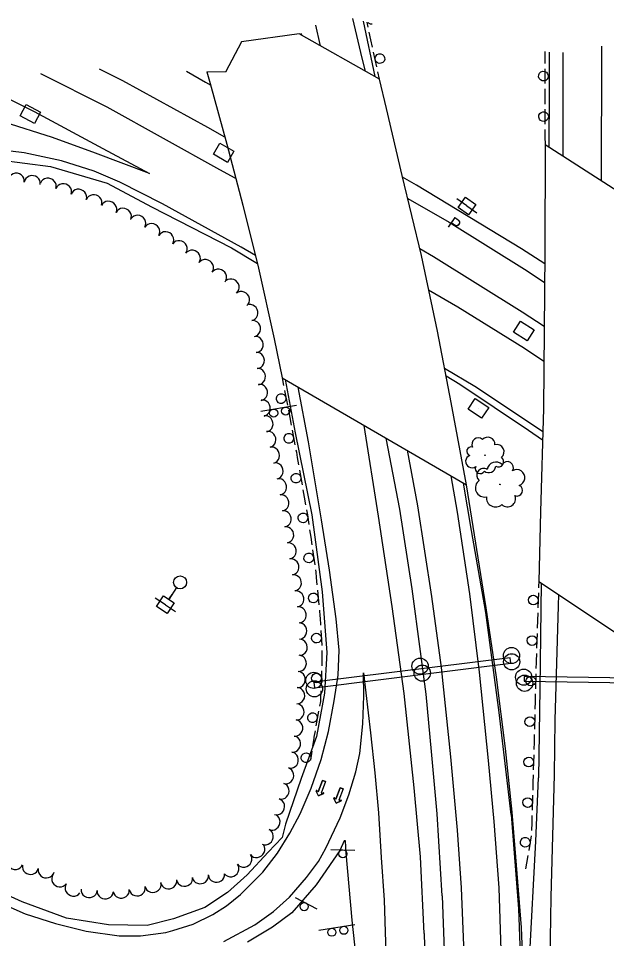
# Model space of a CAD drawing. Extents: x 1746010 to 1754829, y 655801 to 663091.
# Drawn here: x 1753661 to 1754024, y 656968 to 657536 of the extents above; entities that cross this region are included whole.
import ezdxf

# ---------------------------------------------------------------- set-up
doc = ezdxf.new("R2010")
doc.units = 0
for name, color, linetype in [('SURVEY - AERIAL SURVEY - Photo Control - Points - Elevations', 7, 'Continuous'), ('SURVEY - AERIAL SURVEY - Photo Control - Points - Locators', 7, 'Continuous'), ('SURVEY - AERIAL SURVEY - Photo Control - Points - Numbers', 7, 'Continuous'), ('SURVEY - AERIAL SURVEY - Photo Control with Text', 7, 'Continuous'), ('SURVEY - CENTERLINE - Existing Roads Curve Text', 7, 'Continuous'), ('SURVEY - CENTERLINE - Existing Roads Text', 7, 'Continuous'), ('SURVEY - CENTERLINE - Preliminary - Development', 7, 'Continuous'), ('SURVEY - DRAINAGE - Area Shapes - Points - Elevations', 7, 'Continuous')]:
    doc.layers.add(name, color=color, linetype=linetype)

msp = doc.modelspace()

# ---------------------------------------------------------------- linework, layer by layer
at = {"layer": 'SURVEY - AERIAL SURVEY - Photo Control - Points - Elevations'}
for p, q in [((1753834.37, 657526.97), (1753798.75, 657521.92)), ((1753883.94, 657498.81), (1753834.37, 657526.97)), ((1753798.75, 657521.92), (1753789.02, 657503.21)), ((1753789.02, 657503.21), (1753777.4, 657503.5)), ((1753777.4, 657503.5), (1753779.59, 657496.21)), ((1753888.34, 657480.7), (1753883.94, 657498.81)), ((1753779.59, 657496.21), (1753789.79, 657458.68)), ((1753897.95, 657439.39), (1753888.34, 657480.7)), ((1753789.79, 657458.68), (1753799.56, 657421.07)), ((1753909.88, 657390.08), (1753897.95, 657439.39)), ((1753799.56, 657421.07), (1753809.34, 657382.31)), ((1753919.69, 657343.31), (1753909.88, 657390.08)), ((1753809.34, 657382.31), (1753818.96, 657338.7)), ((1753818.96, 657338.7), (1753823.91, 657314.53)), ((1753928.26, 657299.26), (1753919.69, 657343.31)), ((1753823.91, 657314.53), (1753937.73, 657248.53)), ((1753937.73, 657248.53), (1753928.26, 657299.26))]:
    msp.add_line(p, q, dxfattribs=at)
for points in [[(1753982.28, 657188.73), (1754080.08, 657123.8), (1754080.93, 657167.72), (1754082.29, 657253.87), (1754084.25, 657323.66), (1754089.74, 657391.89), (1753986.12, 657458.37), (1753985.99, 657391.93), (1753985.12, 657295.57), (1753983.31, 657231.76)], [(1753983.31, 657231.76), (1753982.28, 657188.73)]]:
    msp.add_lwpolyline(points, dxfattribs=at)
at = {"layer": 'SURVEY - AERIAL SURVEY - Photo Control - Points - Locators'}
for points in [[(1753844.48, 657532.15), (1753847.2, 657520.24), (1753847.35, 657519.6)], [(1753875.26, 657503.74), (1753873.37, 657511.78), (1753867.51, 657536.41)], [(1753874, 657534.62), (1753881.04, 657500.46)], [(1753835.53, 657527.36), (1753835.78, 657526.17)], [(1753988.75, 657515.59), (1753988.61, 657491.19), (1753988.56, 657456.81)], [(1753997.21, 657515.41), (1753997.06, 657451.35)], [(1754020.92, 657436.04), (1754020.94, 657441.6), (1754021.2, 657510.2), (1754021.13, 657519.32)], [(1753788.6, 657463.06), (1753778.14, 657469.07), (1753725.62, 657497.78), (1753711.2, 657505.1)], [(1753764.93, 657503.8), (1753776.54, 657497.13), (1753779.86, 657495.22)], [(1753674.79, 657502.49), (1753715.63, 657481.77), (1753785.31, 657443.07), (1753794.78, 657437.97), (1753795.24, 657437.7)], [(1753637.56, 657495.57), (1753670.88, 657478.92), (1753713.29, 657456.11), (1753741.97, 657440.63), (1753708.7, 657453.2), (1753682.13, 657462.88), (1753652.37, 657472.36)], [(1753807.41, 657389.96), (1753798.71, 657395.14), (1753750.15, 657422.01), (1753723.66, 657435.28), (1753707.83, 657442.08), (1753687.72, 657448.46), (1753664.76, 657453.46), (1753637.56, 657456.66)], [(1753648.98, 657449.1), (1753680.95, 657444.97), (1753716, 657434.66), (1753743.3, 657420.04), (1753792.57, 657394.69), (1753808.62, 657385.12)], [(1753985.93, 657384.86), (1753971.69, 657394.13), (1753906.82, 657433.55), (1753898.17, 657438.46)], [(1753901.37, 657425.25), (1753926.89, 657410.56), (1753975.06, 657380.49), (1753985.82, 657373.37)], [(1753985.58, 657346.15), (1753972.07, 657355.07), (1753917.41, 657389.22), (1753908.91, 657394.1)], [(1753914.32, 657368.9), (1753932.37, 657358.47), (1753973.51, 657332.85), (1753985.39, 657324.89)], [(1753984.71, 657281.22), (1753975.27, 657287.62), (1753942.8, 657309.25), (1753924.15, 657320.36)], [(1753925.05, 657315.77), (1753933.59, 657310.68), (1753975.97, 657282.33), (1753984.57, 657276.37)], [(1753825.7, 657313.49), (1753831.86, 657280.52), (1753842.22, 657229.94), (1753848.55, 657182.4), (1753851.43, 657145.05), (1753849.98, 657119.99), (1753845.04, 657093.08), (1753835.56, 657067.29), (1753825.92, 657038.96), (1753823.95, 657030.83), (1753815.35, 657021.8), (1753802.32, 657007.78), (1753790.24, 656996.9), (1753776.23, 656987.66), (1753756.79, 656980.5), (1753740.58, 656976.5), (1753716.66, 656976.82), (1753690.8, 656981.07), (1753663.52, 656991.15), (1753640.25, 657001.61)], [(1753645.14, 656992.62), (1753665.32, 656983.72), (1753683.97, 656977.73), (1753703.07, 656972.98), (1753723.39, 656970.11), (1753736.43, 656970.12), (1753752.08, 656972.06), (1753756.55, 656973.32), (1753768.99, 656977.37), (1753781.07, 656983.19), (1753789.65, 656988.64), (1753798.13, 656995.69), (1753811.95, 657009.37), (1753821.07, 657021.17), (1753828.6, 657033.44), (1753834.93, 657045.36), (1753841.82, 657061.31), (1753848.04, 657078.86), (1753852.57, 657096.17), (1753856.07, 657115.13), (1753858.57, 657131.1), (1753859.12, 657146.45), (1753857.25, 657165.69), (1753853.03, 657195.87), (1753848.19, 657226.85), (1753840.16, 657275.06), (1753833.88, 657308.74)], [(1753911.58, 656971.59), (1753909.19, 657018.77), (1753905.31, 657061.37), (1753899.14, 657119.66), (1753891.84, 657173.33), (1753883.28, 657229.17), (1753874.58, 657285.15)], [(1753901.01, 657269.83), (1753907.47, 657235.62), (1753916.07, 657179.56), (1753922.04, 657135.77), (1753927.79, 657080.63), (1753932, 657035.33), (1753934.34, 656999.68)], [(1753954.79, 657040.59), (1753951.33, 657078.32), (1753945.71, 657132.8), (1753939.71, 657181.2), (1753932.16, 657231.59), (1753928.27, 657254.02)], [(1753965.29, 657045.03), (1753957.84, 657108.02), (1753949.52, 657169.69), (1753940.73, 657220.37), (1753935.87, 657249.61)], [(1753983.71, 657187.78), (1753983, 657122.71), (1753982.03, 657067.54)], [(1753994.37, 657180.7), (1753994.21, 657173.78), (1753992.14, 657103.3), (1753991.68, 657069.51)], [(1753787.96, 656966.58), (1753807.07, 656976.95), (1753818.65, 656985.21), (1753828.41, 656993.91), (1753838.96, 657006.11), (1753846.27, 657016.03), (1753850.85, 657024.12), (1753859.8, 657042.93), (1753865.11, 657057.06), (1753869.43, 657071.44), (1753871.86, 657082.68), (1753873.77, 657100.96), (1753874.4, 657118.17), (1753874.11, 657132.54), (1753878.36, 657095.43), (1753881.01, 657070.7), (1753883.3, 657046.01), (1753885.02, 657018.43), (1753886.83, 656992.14), (1753888.03, 656953.03)], [(1753965.29, 657045.03), (1753969.78, 656986.81), (1753972.15, 656919.55), (1753972.04, 656909.9), (1753975.16, 656909.61), (1753976.56, 656955.34), (1753980.46, 657028.6), (1753982.03, 657067.54)], [(1753991.68, 657069.51), (1753989.79, 656994.07), (1753988.51, 656917.34), (1753987.63, 656845.93), (1753986.9, 656777.13), (1753986.19, 656713.33), (1753984.5, 656618.92), (1753983.53, 656530.59), (1753982.02, 656453.23), (1753981.29, 656391.76), (1753979.87, 656290.99), (1753978.52, 656188.25), (1753977.29, 656086), (1753975.64, 655980.75), (1753974.7, 655894.53), (1753973.26, 655807.54)], [(1753945.21, 655807.54), (1753945.71, 655839.43), (1753947.46, 655954.84), (1753949.86, 656090.09), (1753951.64, 656208.18), (1753953.96, 656365.1), (1753956.15, 656510.33), (1753958.33, 656633.76), (1753960.21, 656768.19), (1753961.13, 656897.07), (1753957.75, 656999.64), (1753954.79, 657040.59)], [(1753873.7, 656918.81), (1753867.13, 656979.71), (1753863.36, 657021.42), (1753862.98, 657028.83), (1753862.1, 657028.66), (1753859.42, 657022.88), (1753844.95, 657001.52), (1753829.84, 656984.34), (1753818.01, 656975.55), (1753802.43, 656966.23)], [(1753934.34, 656999.68), (1753937.35, 656928.49), (1753937.83, 656848.86), (1753937.15, 656768.64), (1753935.67, 656669.84), (1753934.34, 656582.14), (1753932.9, 656495.46), (1753931.11, 656385.87), (1753929.83, 656290.6), (1753928.48, 656204.07), (1753926.32, 656083.91), (1753924.94, 655990.25), (1753923.13, 655865.62), (1753922.15, 655807.78)], [(1753911.58, 656971.59), (1753912.64, 656934.08), (1753912.82, 656887.25), (1753912.7, 656839.09), (1753911.76, 656786.44), (1753911.02, 656744.09), (1753910.41, 656695.47), (1753910.01, 656636.87), (1753909.36, 656581.72), (1753908.73, 656535.43), (1753907.55, 656485.64), (1753906.86, 656418.94), (1753906.17, 656369.03), (1753905.58, 656318.08), (1753904.54, 656261.45), (1753903.46, 656192.68), (1753902.26, 656132.87), (1753901.8, 656071.81), (1753900.44, 656014.99), (1753899.79, 655943.06), (1753898.72, 655891.08), (1753897.3, 655813.85), (1753897.22, 655808.04)]]:
    msp.add_lwpolyline(points, dxfattribs=at)
at = {"layer": 'SURVEY - AERIAL SURVEY - Photo Control - Points - Numbers'}
for points in [[(1753876.95, 657530.95), (1753876.29, 657533.99)], [(1753834.54, 657526.87), (1753834.52, 657526.99)], [(1753878.63, 657523.23), (1753877.63, 657527.82)], [(1753879.63, 657518.64), (1753878.63, 657523.23)], [(1753882.26, 657506.53), (1753880.31, 657515.51)], [(1753985.92, 657516), (1753985.93, 657513.23)], [(1753985.93, 657513.23), (1753985.95, 657508.54)], [(1753883.94, 657498.81), (1753882.94, 657503.4)], [(1753985.96, 657505.33), (1753985.99, 657496.13)], [(1753986, 657492.93), (1753986.02, 657488.23)], [(1753986.02, 657488.23), (1753986.03, 657483.53)], [(1753986.04, 657480.33), (1753986.07, 657471.13)], [(1753986.09, 657467.93), (1753986.1, 657463.23)], [(1753986.1, 657463.23), (1753986.12, 657458.53)], [(1753823.91, 657314.53), (1753824.79, 657309.91)], [(1753825.4, 657306.77), (1753827.13, 657297.73)], [(1753827.73, 657294.59), (1753828.61, 657289.98)], [(1753828.61, 657289.98), (1753829.5, 657285.36)], [(1753830.1, 657282.22), (1753831.83, 657273.19)], [(1753922.72, 656994.79), (1753919.67, 657045.5), (1753916.14, 657083.96), (1753912.8, 657119.26), (1753909.25, 657145.57), (1753904.05, 657184.38), (1753896.51, 657233.47), (1753888.15, 657277.28)], [(1753832.43, 657270.05), (1753832.68, 657268.75), (1753833.27, 657265.42)], [(1753833.27, 657265.42), (1753834.08, 657260.79)], [(1753834.63, 657257.64), (1753836.22, 657248.58)], [(1753965.85, 657046.35), (1753961.67, 657085.64), (1753956.14, 657129.7), (1753949.81, 657172.53), (1753937.73, 657248.53)], [(1753836.77, 657245.42), (1753837.58, 657240.8)], [(1753837.58, 657240.8), (1753838.39, 657236.17)], [(1753838.95, 657233.01), (1753839.47, 657230.04), (1753840.36, 657223.93)], [(1753840.83, 657220.76), (1753841.51, 657216.12)], [(1753841.51, 657216.12), (1753842.19, 657211.47)], [(1753842.65, 657208.3), (1753843.99, 657199.21)], [(1753844.45, 657196.04), (1753844.65, 657194.66), (1753844.97, 657191.37)], [(1753844.97, 657191.37), (1753845.41, 657186.69)], [(1753982.3, 657189.69), (1753982.14, 657184.99)], [(1753845.71, 657183.51), (1753846.59, 657174.35)], [(1753982.03, 657181.8), (1753981.73, 657172.6)], [(1753846.89, 657171.16), (1753847.24, 657167.47), (1753847.31, 657166.48)], [(1753981.62, 657169.41), (1753981.46, 657164.71)], [(1753847.31, 657166.48), (1753847.61, 657161.79)], [(1753981.46, 657164.71), (1753981.3, 657160.01)], [(1753847.81, 657158.6), (1753848.38, 657149.6), (1753848.38, 657149.42)], [(1753981.19, 657156.81), (1753980.89, 657147.62)], [(1753848.36, 657146.22), (1753848.33, 657141.52)], [(1753848.33, 657141.52), (1753848.31, 657136.82)], [(1753980.62, 657139.73), (1753980.59, 657138.73), (1753980.49, 657135.03)], [(1753980.78, 657144.42), (1753980.62, 657139.73)], [(1753848.29, 657133.62), (1753848.28, 657133.31), (1753847.9, 657124.44)], [(1753980.41, 657131.83), (1753980.18, 657122.63)], [(1753847.77, 657121.24), (1753847.56, 657116.55)], [(1753980.1, 657119.43), (1753979.98, 657114.73)], [(1753847.56, 657116.55), (1753847.49, 657114.81), (1753846.97, 657111.9)], [(1753979.98, 657114.73), (1753979.86, 657110.03)], [(1753846.41, 657108.75), (1753844.79, 657099.7)], [(1753979.78, 657106.83), (1753979.55, 657097.64)], [(1753844.23, 657096.55), (1753843.54, 657092.69), (1753843.43, 657091.92)], [(1753979.47, 657094.44), (1753979.35, 657089.74)], [(1753843.43, 657091.92), (1753842.73, 657087.27)], [(1753979.35, 657089.74), (1753979.23, 657085.04)], [(1753842.25, 657084.11), (1753841.41, 657078.51)], [(1753979.15, 657081.84), (1753979.03, 657077), (1753978.9, 657072.65)], [(1753978.8, 657069.45), (1753978.67, 657064.75)], [(1753978.67, 657064.75), (1753978.53, 657060.05)], [(1753978.44, 657056.85), (1753978.17, 657047.66)], [(1753959.34, 655807.53), (1753959.92, 655877.58), (1753961.6, 655961.39), (1753962.3, 656049.9), (1753963.82, 656144.04), (1753965.44, 656241.01), (1753966.84, 656337.35), (1753968.08, 656438.44), (1753969.78, 656513.74), (1753971.14, 656610.31), (1753972.49, 656678.9), (1753972.99, 656776.8), (1753973.82, 656865.21), (1753973.77, 656924.3), (1753971.68, 656975.27), (1753968.21, 657018.84), (1753965.85, 657046.35)], [(1753978.07, 657044.46), (1753977.93, 657039.76)], [(1753977.93, 657039.76), (1753977.8, 657035.06)], [(1753977.55, 657031.88), (1753976.04, 657022.8)], [(1753974.74, 657015.01), (1753974.14, 657011.38)], [(1753975.52, 657019.65), (1753974.74, 657015.01)], [(1753922.72, 656994.79), (1753925.18, 656927.59), (1753925.98, 656864.35), (1753925.56, 656790.71), (1753924.17, 656722.34), (1753923.24, 656622.61), (1753921.81, 656528.59), (1753920.02, 656430.19), (1753918.5, 656325.43), (1753917.39, 656231.6), (1753914.48, 656115.6), (1753913.35, 656013.48), (1753911.14, 655910.91), (1753909.83, 655807.91)]]:
    msp.add_lwpolyline(points, dxfattribs=at)
for centre, start, end in [((1753878.92, 657536.03), 227.4414, 281.7289), ((1753884.23, 657511.61), 305.5462, 305.5322), ((1753985.13, 657500.77), 97.08, 97.066), ((1753985.22, 657475.77), 97.08, 97.066), ((1753823.31, 657301.73), 124.117, 124.103), ((1753828.01, 657277.19), 124.117, 124.103), ((1753832.46, 657252.63), 123.2066, 123.1926), ((1753836.72, 657228.09), 121.6112, 121.5972), ((1753840.34, 657203.37), 121.6112, 121.5972), ((1753843.16, 657178.69), 118.7104, 118.6964), ((1753978.95, 657177.33), 110.9042, 110.8903), ((1753845.11, 657153.86), 116.9166, 116.9026), ((1753978.11, 657152.35), 110.9042, 110.8903), ((1753845.11, 657129.21), 110.8214, 110.8074), ((1753977.37, 657127.35), 111.3358, 111.3218), ((1753842.66, 657104.8), 103.1534, 103.1394), ((1753976.74, 657102.36), 111.3358, 111.3218), ((1753838.61, 657080.05), 104.7147, 104.7007), ((1753976.1, 657077.36), 111.3358, 111.3218), ((1753975.37, 657052.38), 111.1344, 111.1204), ((1753973.91, 657027.87), 103.3191, 103.3051)]:
    msp.add_arc(centre, 3, start, end, dxfattribs=at)
at = {"layer": 'SURVEY - AERIAL SURVEY - Photo Control with Text'}
for p, q in [((1753810.71, 657293.88), (1753832.79, 657297.67)), ((1753965.44, 657143.1), (1753965.44, 657143.1)), ((1753909.02, 657136.55), (1753909.02, 657136.55)), ((1753965.54, 657139.23), (1753965.54, 657139.23)), ((1753910.36, 657132.24), (1753910.36, 657132.24)), ((1753972.99, 657129.75), (1753972.99, 657129.75)), ((1753843.47, 657127.74), (1753843.47, 657127.74)), ((1753843.84, 657122.54), (1753843.84, 657122.54)), ((1753973.53, 657125.97), (1753973.53, 657125.97)), ((1753853.86, 657023.39), (1753868.85, 657023.01)), ((1753832.03, 656993.86), (1753845.24, 656986.76)), ((1753846.62, 656973.5), (1753868.73, 656977.11))]:
    msp.add_line(p, q, dxfattribs=at)
for points in [[(1753843.93, 657123.25), (1753964.99, 657138.43), (1753964.56, 657141.78), (1753843.51, 657126.6)], [(1753973.26, 657127.29), (1754052.64, 657126.07), (1754052.68, 657128.89), (1753973.3, 657130.11)]]:
    msp.add_lwpolyline(points, close=True, dxfattribs=at)
for centre, radius in [((1753818.66, 657292.76), 2.5), ((1753826.05, 657294.03), 2.5), ((1753965.45, 657143.14), 5), ((1753909.03, 657136.58), 5), ((1753965.54, 657139.27), 5), ((1753910.37, 657132.28), 5), ((1753972.98, 657129.79), 5), ((1753843.46, 657127.78), 5), ((1753973.52, 657126.01), 5), ((1753843.83, 657122.58), 5), ((1753861.34, 657020.75), 2.5), ((1753837.51, 656988.13), 2.5), ((1753854.56, 656972.32), 2.5), ((1753861.96, 656973.53), 2.5)]:
    msp.add_circle(centre, radius, dxfattribs=at)
at = {"layer": 'SURVEY - CENTERLINE - Existing Roads Curve Text'}
for p, q in [((1753937.9, 657420.7), (1753931.77, 657425.01)), ((1753937.9, 657420.7), (1753944.03, 657416.38)), ((1753758.79, 657185.02), (1753754, 657177.76)), ((1753754.22, 657178.09), (1753755.98, 657180.77)), ((1753751.85, 657174.51), (1753745.59, 657178.64)), ((1753751.85, 657174.51), (1753758.11, 657170.38))]:
    msp.add_line(p, q, dxfattribs=at)
for points in [[(1753936.96, 657426.13), (1753943.33, 657421.64), (1753938.84, 657415.26), (1753932.47, 657419.75)], [(1753746.45, 657173.4), (1753750.74, 657179.91), (1753757.25, 657175.61), (1753752.96, 657169.1)]]:
    msp.add_lwpolyline(points, close=True, dxfattribs=at)
msp.add_circle((1753760.94, 657188.28), 4, dxfattribs=at)
at = {"layer": 'SURVEY - CENTERLINE - Existing Roads Text'}
for centre, radius in [((1753949.08, 657266.79), 0.138), ((1753958.28, 657248.74), 0.174)]:
    msp.add_circle(centre, radius, dxfattribs=at)
for centre, radius, start, end in [((1753944.94, 657273.51), 3.95, 49.4933, 206.2823), ((1753950.74, 657273.39), 4.5, 358.5461, 136.0703), ((1753940.54, 657269.18), 2.71, 71.6095, 250.3551), ((1753956.41, 657268.97), 4.47, 309.4419, 105.2804), ((1753941.08, 657262.97), 3.94, 111.6302, 305.0499), ((1753957.35, 657262.82), 3.3, 239.6948, 54.6951), ((1753946.05, 657258.44), 3, 154.2488, 331.568), ((1753948.17, 657254.45), 4.17, 55.8749, 230.8752), ((1753951.44, 657260.24), 4.25, 229.5359, 356.3816), ((1753955.85, 657257.21), 5.38, 45.716, 172.5616), ((1753962.81, 657259.04), 3.8, 330.4289, 147.7481), ((1753968.7, 657252.9), 4.99, 287.8102, 121.2299), ((1753948.83, 657246.62), 5.66, 125.622, 281.4605), ((1753968.86, 657245), 3.43, 247.7896, 66.5352), ((1753962.94, 657239.91), 5, 225.6734, 22.4623), ((1753955.63, 657240.55), 5.7, 174.7261, 312.2504)]:
    msp.add_arc(centre, radius, start, end, dxfattribs=at)
for centre, major_axis in [((1753659.81, 657436.14), (4.95, -0.74)), ((1753669.7, 657434.66), (4.95, -0.74)), ((1753679.56, 657433.05), (4.7, -1.7)), ((1753688.96, 657429.65), (4.7, -1.7)), ((1753698.36, 657426.24), (4.7, -1.7)), ((1753707.77, 657422.84), (4.7, -1.7)), ((1753716.91, 657418.82), (4.51, -2.16)), ((1753725.93, 657414.5), (4.51, -2.16)), ((1753734.91, 657410.1), (4.3, -2.55)), ((1753743.51, 657405), (4.3, -2.55)), ((1753752.12, 657399.91), (4.3, -2.55)), ((1753760.47, 657394.43), (4.05, -2.93)), ((1753768.56, 657388.58), (4.05, -2.93)), ((1753776.66, 657382.72), (4.05, -2.94)), ((1753784.75, 657376.84), (4.05, -2.94)), ((1753792.59, 657370.7), (3.17, -3.87)), ((1753798.93, 657362.97), (3.17, -3.87)), ((1753804.26, 657354.78), (0.85, -4.93)), ((1753805.95, 657344.95), (0.85, -4.93)), ((1753807.57, 657335.12), (0.34, -4.99)), ((1753808.24, 657325.22), (0.34, -4.99)), ((1753808.91, 657315.31), (0.34, -4.99)), ((1753810.15, 657305.54), (0.87, -4.92)), ((1753811.86, 657295.87), (0.87, -4.92)), ((1753813.58, 657286.21), (0.87, -4.92)), ((1753815.35, 657276.53), (1.11, -4.87)), ((1753817.57, 657266.79), (1.11, -4.87)), ((1753819.8, 657257.04), (1.11, -4.87)), ((1753821.93, 657247.27), (0.73, -4.95)), ((1753823.39, 657237.38), (0.73, -4.95)), ((1753824.84, 657227.48), (0.73, -4.95)), ((1753826.34, 657217.6), (0.8, -4.94)), ((1753827.94, 657207.72), (0.8, -4.94)), ((1753829.53, 657197.85), (0.8, -4.94)), ((1753831.08, 657187.98), (0.76, -4.94)), ((1753832.59, 657178.1), (0.76, -4.94)), ((1753834.1, 657168.23), (0.76, -4.94)), ((1753834.44, 657158.24), (0.13, -5)), ((1753834.7, 657148.25), (0.13, -5)), ((1753834.16, 657138.28), (-0.32, -4.99)), ((1753833.52, 657128.32), (-0.32, -4.99)), ((1753833.12, 657118.34), (-0.18, -5)), ((1753832.75, 657108.34), (-0.18, -5)), ((1753831.94, 657098.39), (-0.68, -4.95)), ((1753830.57, 657088.49), (-0.68, -4.95)), ((1753829.21, 657078.58), (-0.68, -4.95)), ((1753826.37, 657069), (-1.46, -4.78)), ((1753823.48, 657059.43), (-1.4, -4.8)), ((1753820.67, 657049.83), (-1.4, -4.8)), ((1753817.85, 657040.24), (-2.09, -4.54)), ((1753813.71, 657031.24), (-2.09, -4.54)), ((1753808.34, 657023.23), (-4.01, -2.99)), ((1753800.37, 657017.28), (-4.01, -2.99)), ((1753659.1, 657015.8), (-4.65, 1.85)), ((1753668.56, 657012.7), (-4.88, 1.09)), ((1753678.27, 657010.54), (-4.88, 1.09)), ((1753792.39, 657011.34), (-4.01, -2.99)), ((1753686.6, 657005.05), (-4.13, 2.82)), ((1753753.92, 657003.84), (-4.94, -0.79)), ((1753763.7, 657005.39), (-4.94, -0.79)), ((1753773.47, 657006.95), (-4.94, -0.79)), ((1753783.42, 657007.92), (-4.98, -0.47)), ((1753694.86, 656999.41), (-4.13, 2.82)), ((1753704.78, 656998.45), (-4.98, 0.45)), ((1753714.73, 656997.56), (-4.98, 0.45)), ((1753724.63, 656998.05), (-4.96, -0.64)), ((1753734.48, 656999.43), (-4.88, -1.11)), ((1753744.2, 657001.64), (-4.88, -1.11))]:
    msp.add_ellipse(centre, major_axis=major_axis, ratio=0.940188, start_param=0, end_param=3.141593, dxfattribs=at)
at = {"layer": 'SURVEY - CENTERLINE - Preliminary - Development'}
for p, q in [((1753668.52, 657477.43), (1753668.52, 657477.43)), ((1753787.77, 657453.51), (1753787.77, 657453.51)), ((1753973.03, 657343.42), (1753973.03, 657343.42)), ((1753944.98, 657295.74), (1753944.98, 657295.74))]:
    msp.add_line(p, q, dxfattribs=at)
for points in [[(1753662.23, 657476.27), (1753666.01, 657483.32), (1753674.82, 657478.59), (1753671.04, 657471.54), (1753662.23, 657476.27)], [(1753794.1, 657454.49), (1753790.12, 657447.55), (1753781.45, 657452.53), (1753785.43, 657459.46), (1753794.1, 657454.49)], [(1753979.39, 657344.14), (1753975.12, 657337.37), (1753966.66, 657342.71), (1753970.93, 657349.48), (1753979.39, 657344.14)], [(1753938.61, 657295.16), (1753943.01, 657301.84), (1753951.36, 657296.33), (1753946.95, 657289.65), (1753938.61, 657295.16)]]:
    msp.add_lwpolyline(points, dxfattribs=at)
at = {"layer": 'SURVEY - DRAINAGE - Area Shapes - Points - Elevations'}
for p, q in [((1753846.22, 657058.93), (1753848.75, 657066.02)), ((1753848.75, 657066.02), (1753846.22, 657058.93)), ((1753848.75, 657066.02), (1753850.6, 657065.36)), ((1753850.6, 657065.36), (1753848.75, 657066.02)), ((1753850.6, 657065.36), (1753848.07, 657058.27)), ((1753850.6, 657065.36), (1753848.07, 657058.27)), ((1753857.11, 657054.47), (1753859.63, 657061.56)), ((1753859.63, 657061.56), (1753857.11, 657054.47)), ((1753861.49, 657060.9), (1753858.96, 657053.81)), ((1753861.49, 657060.9), (1753858.96, 657053.81)), ((1753859.63, 657061.56), (1753861.49, 657060.9)), ((1753861.49, 657060.9), (1753859.63, 657061.56)), ((1753846.37, 657056.42), (1753844.92, 657059.47)), ((1753846.37, 657056.42), (1753844.92, 657059.47)), ((1753845.31, 657059.76), (1753846.22, 657058.93)), ((1753846.22, 657058.93), (1753845.31, 657059.76)), ((1753849.42, 657057.86), (1753846.37, 657056.42)), ((1753846.37, 657056.42), (1753849.42, 657057.86)), ((1753848.07, 657058.27), (1753849.3, 657058.33)), ((1753848.07, 657058.27), (1753849.3, 657058.33)), ((1753857.26, 657051.96), (1753855.81, 657055.01)), ((1753857.26, 657051.96), (1753855.81, 657055.01)), ((1753856.2, 657055.3), (1753857.11, 657054.47)), ((1753857.11, 657054.47), (1753856.2, 657055.3)), ((1753860.31, 657053.41), (1753857.26, 657051.96)), ((1753857.26, 657051.96), (1753860.31, 657053.41)), ((1753858.96, 657053.81), (1753860.19, 657053.88)), ((1753858.96, 657053.81), (1753860.19, 657053.88))]:
    msp.add_line(p, q, dxfattribs=at)
for centre, start, end in [((1753845.14, 657059.57), 47.9442, 205.3925), ((1753845.14, 657059.57), 47.9442, 205.3925), ((1753849.31, 657058.09), 295.3925, 92.8856), ((1753849.31, 657058.09), 295.3925, 92.8856), ((1753856.03, 657055.12), 47.9442, 205.3925), ((1753856.03, 657055.12), 47.9442, 205.3925), ((1753860.2, 657053.63), 295.3925, 92.8856), ((1753860.2, 657053.63), 295.3925, 92.8856)]:
    msp.add_arc(centre, 0.246, start, end, dxfattribs=at)

# ---------------------------------------------------------------- texts
at = {"layer": 'SURVEY - CENTERLINE - Existing Roads Curve Text'}
msp.add_text('P', height=7.48, rotation=324.8392, dxfattribs=at).set_placement((1753925.4, 657408.34))

doc.saveas('drawing.dxf')
